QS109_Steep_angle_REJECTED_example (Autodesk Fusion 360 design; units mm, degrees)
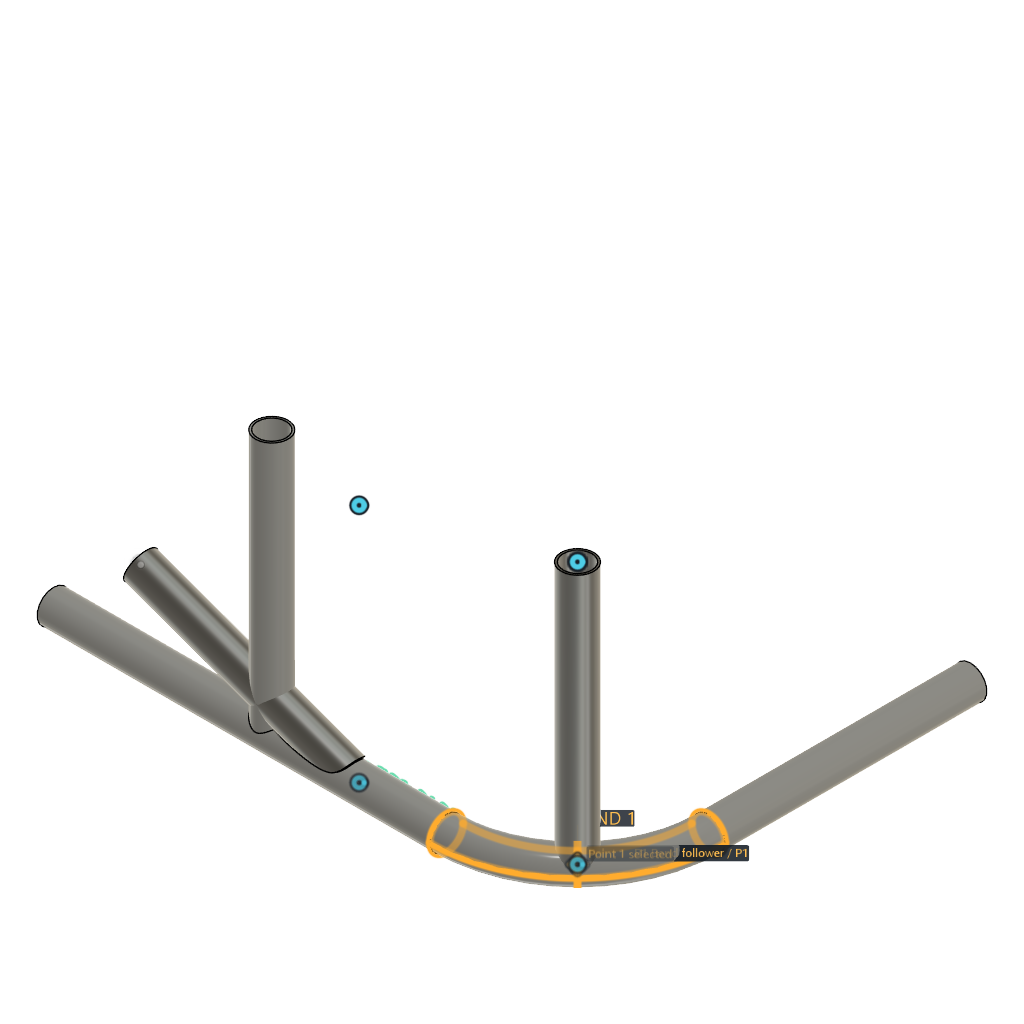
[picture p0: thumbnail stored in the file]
description: Part Number
part number: 2026-10-26-11-38-19-526
parameter "OD_DEMO_ONLY_1_5_x_095_R6" = 38.1
parameter "Wall_DEMO_ONLY_1_5_x_095_R6" = 2.413
base_feature "Base Feature1" bodies "H1 Bent host", "I1 Imported coped brace"
sketch "Tube points" plane through (0, 0, 0) normal (0, 0, 1) x axis (1, 0, 0)
sketch "TubePoints" plane through (0, 0, 0) normal (0, 0, 1) x axis (1, 0, 0)
work_plane "WorkPlane1" ExtraOffset 0
sketch "Sketch3" plane through (564.9631, 44.6369, 0) normal (0, 0, 1) x axis (0, 1, 0)
  circle C1 centre (0, 0) radius 19.05
  circle C2 centre (0, 0) radius 16.637
sketch "TubePoints (1)" plane through (0, 0, 0) normal (0, 0, 1) x axis (1, 0, 0)
work_plane "WorkPlane2" ExtraOffset 0
sketch "Sketch5" plane through (355.6, 0, 0) normal (0, 0, 1) x axis (0, 1, 0)
  circle C1 centre (0, 0) radius 19.05
  circle C2 centre (0, 0) radius 16.637
sketch "TubePoints (2)" plane through (0, 0, 0) normal (0, 0, 1) x axis (1, 0, 0)
work_plane "WorkPlane3" ExtraOffset 0
sketch "Sketch7" plane through (564.9631, 44.6369, 0) normal (0, 0, 1) x axis (0, 1, 0)
  circle C1 centre (0, 0) radius 19.05
  circle C2 centre (0, 0) radius 16.637
  dimension "d21" diameter C1 = 38.1 (= "OD_DEMO_ONLY_1_5_x_095_R6")
  dimension "d22" diameter C2 = 33.274 (= "OD_DEMO_ONLY_1_5_x_095_R6 - 2 * Wall_DEMO_ONLY_1_5_x_095_R6")
sweep "Sweep3" sketch "Sketch7" TwistAngle 0 TaperAngle 0 bodies "B1 Bend follower"
sketch "TubePoints (3)" plane through (0, 0, 0) normal (0, 0, 1) x axis (1, 0, 0)
  line L1 (101.6, 0) -> (355.6, 0)
work_plane "WorkPlane4" ExtraOffset 0
sketch "Sketch9" plane through (355.6, 0, 0) normal (-0.9397, 0, 0.342) x axis (0.342, 0, 0.9397)
  circle C1 centre (0, 0) radius 19.05
  circle C2 centre (0, 0) radius 16.637
  dimension "d31" diameter C1 = 38.1 (= "OD_DEMO_ONLY_1_5_x_095_R6")
  dimension "d32" diameter C2 = 33.274 (= "OD_DEMO_ONLY_1_5_x_095_R6 - 2 * Wall_DEMO_ONLY_1_5_x_095_R6")
sweep "Sweep4" sketch "Sketch9" TwistAngle 0 TaperAngle 0 bodies "B2 Straight joint"
base_feature "Base Feature2"
surface_stitch "SurfaceStitch1" StitchingTolerence 0.01 bodies "normcope_B2_Straight_joint_A"
split "Split1" bodies "B2 Straight joint"
remove_body "RemoveBody1"
remove_body "RemoveBody2"
base_feature "Base Feature3"
combine "Combine1"
named bodies: "H1 Bent host", "I1 Imported coped brace", "B1 Bend follower", "B2 Straight joint", "normcope_B2_Straight_joint_A"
